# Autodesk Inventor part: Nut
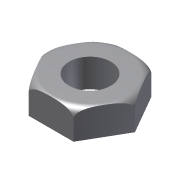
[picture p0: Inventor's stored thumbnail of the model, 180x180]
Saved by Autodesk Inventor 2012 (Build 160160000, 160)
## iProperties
Created: 2009-04
Part Number: Nut
Document SubType Name: Modeling
Designer: Sham
Density: 1 g/cm^3
Material: Default
Author: Sham
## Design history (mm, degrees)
sketch "Sketch1"
  geometry: L1 (19.919, 34.5)-(39.837, 0); L2 (39.837, 0)-(19.919, -34.5); L3 (19.919, -34.5)-(-19.919, -34.5); L4 (-19.919, -34.5)-(-39.837, 0); L5 (-39.837, 0)-(-19.919, 34.5); L6 (-19.919, 34.5)-(19.919, 34.5); C1 r 18.5 at (0, 0); 1 further point
  constraints: 12 end point, 1 centre point, 1 coincident, 13 other
  dimensions: "d0" = 69 distance between parallel lines of L3 L6; "d1" = 37 diameter of C1
extrude "Extrusion1" new body sketch "Sketch1" distance "d2" = 25; taper "d3" = 0 deg
sketch "Sketch2"
  geometry: L1 (0, -5.4)-(0, 32.4) reference; L2 (-19.919, 25)-(-39.837, 25) reference; L3 (-19.919, 25)-(-39.837, 25) reference; L4 (-39.837, 0)-(-39.837, 25) reference; L5 (-19.919, 0)-(-39.837, 0) reference; L6 (-19.919, 0)-(-19.919, 25) reference; A1 r 7.5 centre (-32.337, 17.5) between (-32.337, 25) and (-39.837, 17.5); 1 further point
  constraints: 2 midpoint, 2 point on circle, 2 point on line, 2 tangent, 1 centre point
  dimensions: "d6" = 7.5 radius of A1
revolve "Revolution1" sketch "Sketch2" stored, may be unused: angle "d5" = 90 deg
body "Solid1"
node "Projected Loop1"
other parameters: "d4" = 90 deg
